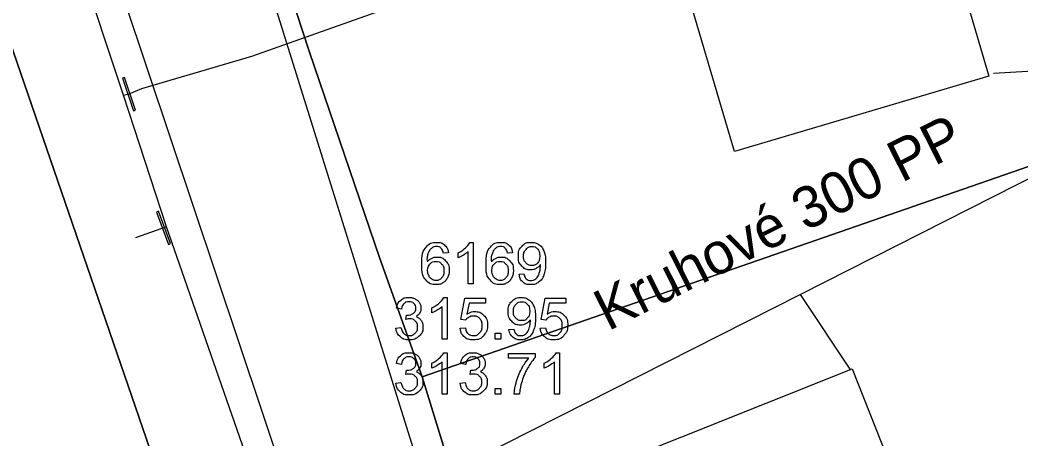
# Model space of a CAD drawing. Extents: x -562248 to -562040, y -1079385 to -1079027.
# Drawn here: x -562123.63 to -562087.3, y -1079164.97 to -1079149.79 of the extents above; entities that cross this region are included whole.
import ezdxf

# ---------------------------------------------------------------- set-up
doc = ezdxf.new("R2010")
doc.units = 0
for name, color, linetype in [('Armatura vodovodní', 7, 'Continuous'), ('Kanalizační přípojka', 7, 'Continuous'), ('Kanalizační stoka', 7, 'Continuous'), ('Parcela-polygon', 7, 'Continuous'), ('Popis kmenové stoky', 7, 'Continuous'), ('Popis šachty', 7, 'Continuous'), ('Vodovodní přípojka', 7, 'Continuous'), ('Vodovodní řad', 7, 'Continuous')]:
    doc.layers.add(name, color=color, linetype=linetype)

msp = doc.modelspace()

# ---------------------------------------------------------------- linework, layer by layer
at = {"layer": 'Armatura vodovodní'}
for points in [[(-562119.512, -1079153.079), (-562119.438, -1079153.054), (-562119.841, -1079151.871), (-562119.915, -1079151.896)], [(-562118.243, -1079157.919), (-562118.17, -1079157.891), (-562118.608, -1079156.721), (-562118.681, -1079156.748)]]:
    msp.add_lwpolyline(points, close=True, dxfattribs=at)
at = {"layer": 'Kanalizační přípojka'}
for points in [[(-562088.3, -1079151.71), (-562084.597, -1079151.5)], [(-562093.48, -1079162.48), (-562095.299, -1079159.731)]]:
    msp.add_lwpolyline(points, dxfattribs=at)
at = {"layer": 'Kanalizační stoka'}
for points in [[(-562118.27, -1079136.83), (-562108.95, -1079166.63)], [(-562098.95, -1079211.35), (-562123.19, -1079139.07)], [(-562083.94, -1079153.99), (-562095.303, -1079159.733), (-562108.95, -1079166.63)]]:
    msp.add_lwpolyline(points, dxfattribs=at)
at = {"layer": 'Parcela-polygon'}
for points in [[(-562074.7, -1079253.09), (-562081.96, -1079237.32), (-562088.81, -1079221.44), (-562094.66, -1079207.06), (-562098.96, -1079196.12), (-562103.67, -1079183.92), (-562101.64, -1079183.14), (-562108.26, -1079165.24), (-562109.03, -1079162.72), (-562110.57, -1079158.43), (-562113.13, -1079150.92), (-562115.47, -1079143.79), (-562118.94, -1079132.53), (-562120.22, -1079128.2), (-562121.94, -1079119.29), (-562122.55, -1079115.89), (-562122.79, -1079112.89), (-562122.92, -1079108.96), (-562122.69, -1079105.05), (-562122.05, -1079101.16)], [(-562097.98, -1079104.526), (-562122.92, -1079108.96), (-562122.79, -1079112.89), (-562122.55, -1079115.89), (-562121.94, -1079119.29), (-562120.22, -1079128.2), (-562118.94, -1079132.53), (-562115.47, -1079143.79), (-562113.13, -1079150.92), (-562110.57, -1079158.43), (-562109.03, -1079162.72), (-562081.378, -1079153.144)], [(-562101.27, -1079108.39), (-562097, -1079122.85), (-562092.73, -1079137.34), (-562088.46, -1079151.82), (-562097.7, -1079154.55), (-562101.98, -1079140.06), (-562106.25, -1079125.58), (-562110.52, -1079111.1), (-562101.27, -1079108.39)], [(-562130.204, -1079213.482), (-562129.52, -1079213.24), (-562126.56, -1079212.06), (-562110.18, -1079204.89), (-562109.412, -1079204.67), (-562108.694, -1079204.319), (-562108.049, -1079203.848), (-562107.496, -1079203.271), (-562107.054, -1079202.606), (-562106.734, -1079201.874), (-562106.547, -1079201.097), (-562106.5, -1079200.3), (-562107.01, -1079197.84), (-562112.9, -1079182.58), (-562117.83, -1079168.5), (-562124.14, -1079150.14), (-562125.7, -1079148.16), (-562127.71, -1079147.6), (-562130.14, -1079147.9), (-562151.942, -1079151.733)], [(-562151.942, -1079151.733), (-562130.14, -1079147.9), (-562127.71, -1079147.6), (-562125.7, -1079148.16), (-562124.14, -1079150.14), (-562117.83, -1079168.5), (-562112.9, -1079182.58), (-562107.01, -1079197.84), (-562106.5, -1079200.3), (-562100.28, -1079214.7), (-562095.19, -1079227.16), (-562092.25, -1079234.14), (-562087.93, -1079243.96)], [(-562081.378, -1079153.144), (-562109.03, -1079162.72), (-562108.26, -1079165.24), (-562101.64, -1079183.14), (-562103.67, -1079183.92), (-562098.96, -1079196.12), (-562094.66, -1079207.06), (-562088.81, -1079221.44), (-562081.96, -1079237.32), (-562074.7, -1079253.09), (-562050.734, -1079242.89)], [(-562096.6, -1079181.53), (-562102.73, -1079166.14), (-562093.43, -1079162.43), (-562091.11, -1079168.27), (-562089.23, -1079167.52), (-562087.59, -1079171.57), (-562089.45, -1079172.36), (-562087.31, -1079177.84), (-562084.66, -1079184.52)]]:
    msp.add_lwpolyline(points, dxfattribs=at)
for points in [[(-562092.73, -1079137.34), (-562088.46, -1079151.82), (-562097.7, -1079154.55), (-562101.98, -1079140.06)], [(-562091.11, -1079168.27), (-562089.23, -1079167.52), (-562087.59, -1079171.57), (-562089.45, -1079172.36), (-562087.31, -1079177.84), (-562096.6, -1079181.53), (-562102.73, -1079166.14), (-562093.43, -1079162.43)]]:
    msp.add_lwpolyline(points, close=True, dxfattribs=at)
at = {"layer": 'Popis šachty'}
for points in [[(-562107.298, -1079157.846), (-562107.18, -1079157.846), (-562107.18, -1079159.352)], [(-562108.081, -1079158.22), (-562108.264, -1079158.235)], [(-562107.732, -1079158.401), (-562107.732, -1079158.223)], [(-562107.18, -1079159.352), (-562107.364, -1079159.352), (-562107.364, -1079158.179)], [(-562105.751, -1079158.22), (-562105.933, -1079158.235)], [(-562105.515, -1079159.004), (-562105.338, -1079158.988)], [(-562108.248, -1079159.846), (-562108.129, -1079159.846), (-562108.129, -1079161.352)], [(-562107.451, -1079160.665), (-562107.624, -1079160.642), (-562107.479, -1079159.871), (-562106.733, -1079159.871), (-562106.733, -1079160.047), (-562107.331, -1079160.047), (-562107.412, -1079160.45)], [(-562104.539, -1079160.665), (-562104.712, -1079160.642), (-562104.567, -1079159.871), (-562103.821, -1079159.871), (-562103.821, -1079160.047), (-562104.419, -1079160.047), (-562104.5, -1079160.45)], [(-562109.783, -1079160.268), (-562109.968, -1079160.235)], [(-562108.681, -1079160.401), (-562108.681, -1079160.223)], [(-562108.129, -1079161.352), (-562108.313, -1079161.352), (-562108.313, -1079160.179)], [(-562109.623, -1079160.641), (-562109.602, -1079160.48)], [(-562109.986, -1079160.954), (-562109.802, -1079160.93)], [(-562107.657, -1079160.959), (-562107.464, -1079160.943)], [(-562104.745, -1079160.959), (-562104.552, -1079160.943)], [(-562106.389, -1079161.352), (-562106.389, -1079161.143), (-562106.18, -1079161.143), (-562106.18, -1079161.352), (-562106.389, -1079161.352)], [(-562105.883, -1079161.004), (-562105.705, -1079160.988)], [(-562108.248, -1079161.846), (-562108.129, -1079161.846), (-562108.129, -1079163.352)], [(-562105.897, -1079162.049), (-562105.897, -1079161.871), (-562104.927, -1079161.871), (-562104.927, -1079162.015)], [(-562105.163, -1079162.049), (-562105.897, -1079162.049)], [(-562104.171, -1079161.846), (-562104.052, -1079161.846), (-562104.052, -1079163.352)], [(-562109.783, -1079162.268), (-562109.968, -1079162.235)], [(-562108.681, -1079162.401), (-562108.681, -1079162.223)], [(-562108.129, -1079163.352), (-562108.313, -1079163.352), (-562108.313, -1079162.179)], [(-562107.453, -1079162.268), (-562107.637, -1079162.235)], [(-562104.604, -1079162.401), (-562104.604, -1079162.223)], [(-562104.052, -1079163.352), (-562104.236, -1079163.352), (-562104.236, -1079162.179)], [(-562109.623, -1079162.641), (-562109.602, -1079162.48)], [(-562107.293, -1079162.641), (-562107.272, -1079162.48)], [(-562109.986, -1079162.954), (-562109.802, -1079162.93)], [(-562107.656, -1079162.954), (-562107.472, -1079162.93)], [(-562106.389, -1079163.352), (-562106.389, -1079163.143), (-562106.18, -1079163.143), (-562106.18, -1079163.352), (-562106.389, -1079163.352)], [(-562105.498, -1079163.352), (-562105.688, -1079163.352)]]:
    msp.add_lwpolyline(points, dxfattribs=at)
for points in [[(-562108.264, -1079158.235), (-562108.288, -1079158.126), (-562108.333, -1079158.076), (-562108.408, -1079157.997), (-562108.518, -1079157.997), (-562108.606, -1079157.997), (-562108.673, -1079158.046), (-562108.76, -1079158.11), (-562108.81, -1079158.232), (-562108.861, -1079158.353), (-562108.863, -1079158.578), (-562108.796, -1079158.477), (-562108.7, -1079158.428), (-562108.603, -1079158.379), (-562108.498, -1079158.379), (-562108.313, -1079158.379), (-562108.184, -1079158.514), (-562108.054, -1079158.65), (-562108.054, -1079158.865), (-562108.054, -1079159.006), (-562108.115, -1079159.127), (-562108.176, -1079159.248), (-562108.283, -1079159.313), (-562108.389, -1079159.377), (-562108.524, -1079159.377), (-562108.755, -1079159.377), (-562108.9, -1079159.208), (-562109.046, -1079159.039), (-562109.046, -1079158.65), (-562109.046, -1079158.215), (-562108.885, -1079158.018), (-562108.744, -1079157.846), (-562108.507, -1079157.846), (-562108.33, -1079157.846), (-562108.216, -1079157.946), (-562108.103, -1079158.045), (-562108.081, -1079158.22)], [(-562107.732, -1079158.223), (-562107.577, -1079158.15), (-562107.462, -1079158.047), (-562107.346, -1079157.943), (-562107.298, -1079157.846)], [(-562105.933, -1079158.235), (-562105.958, -1079158.126), (-562106.003, -1079158.076), (-562106.078, -1079157.997), (-562106.188, -1079157.997), (-562106.276, -1079157.997), (-562106.343, -1079158.046), (-562106.43, -1079158.11), (-562106.48, -1079158.232), (-562106.531, -1079158.353), (-562106.533, -1079158.578), (-562106.466, -1079158.477), (-562106.37, -1079158.428), (-562106.273, -1079158.379), (-562106.168, -1079158.379), (-562105.983, -1079158.379), (-562105.854, -1079158.514), (-562105.724, -1079158.65), (-562105.724, -1079158.865), (-562105.724, -1079159.006), (-562105.785, -1079159.127), (-562105.846, -1079159.248), (-562105.953, -1079159.313), (-562106.059, -1079159.377), (-562106.194, -1079159.377), (-562106.425, -1079159.377), (-562106.57, -1079159.208), (-562106.715, -1079159.039), (-562106.715, -1079158.65), (-562106.715, -1079158.215), (-562106.555, -1079158.018), (-562106.414, -1079157.846), (-562106.177, -1079157.846), (-562105.999, -1079157.846), (-562105.886, -1079157.946), (-562105.773, -1079158.045), (-562105.751, -1079158.22)], [(-562105.338, -1079158.988), (-562105.315, -1079159.113), (-562105.252, -1079159.17), (-562105.189, -1079159.226), (-562105.09, -1079159.226), (-562105.005, -1079159.226), (-562104.941, -1079159.187), (-562104.876, -1079159.148), (-562104.836, -1079159.083), (-562104.795, -1079159.018), (-562104.768, -1079158.908), (-562104.74, -1079158.797), (-562104.74, -1079158.682), (-562104.74, -1079158.67), (-562104.741, -1079158.646), (-562104.796, -1079158.734), (-562104.892, -1079158.788), (-562104.987, -1079158.843), (-562105.099, -1079158.843), (-562105.285, -1079158.843), (-562105.414, -1079158.708), (-562105.542, -1079158.573), (-562105.542, -1079158.352), (-562105.542, -1079158.124), (-562105.408, -1079157.985), (-562105.274, -1079157.846), (-562105.071, -1079157.846), (-562104.925, -1079157.846), (-562104.804, -1079157.925), (-562104.683, -1079158.004), (-562104.62, -1079158.149), (-562104.557, -1079158.295), (-562104.557, -1079158.571), (-562104.557, -1079158.859), (-562104.619, -1079159.029), (-562104.682, -1079159.199), (-562104.805, -1079159.288), (-562104.928, -1079159.377), (-562105.094, -1079159.377), (-562105.27, -1079159.377), (-562105.381, -1079159.279), (-562105.493, -1079159.181), (-562105.515, -1079159.004)], [(-562104.762, -1079158.343), (-562104.762, -1079158.184), (-562104.846, -1079158.091), (-562104.929, -1079157.998), (-562105.048, -1079157.998), (-562105.172, -1079157.998), (-562105.262, -1079158.099), (-562105.353, -1079158.199), (-562105.353, -1079158.358), (-562105.353, -1079158.502), (-562105.267, -1079158.591), (-562105.181, -1079158.681), (-562105.054, -1079158.681), (-562104.926, -1079158.681), (-562104.844, -1079158.591), (-562104.762, -1079158.502), (-562104.762, -1079158.343)], [(-562107.364, -1079158.179), (-562107.43, -1079158.242), (-562107.538, -1079158.305), (-562107.646, -1079158.369), (-562107.732, -1079158.401)], [(-562108.834, -1079158.866), (-562108.834, -1079158.961), (-562108.794, -1079159.048), (-562108.753, -1079159.135), (-562108.681, -1079159.181), (-562108.609, -1079159.226), (-562108.528, -1079159.226), (-562108.411, -1079159.226), (-562108.328, -1079159.132), (-562108.244, -1079159.038), (-562108.244, -1079158.876), (-562108.244, -1079158.72), (-562108.327, -1079158.631), (-562108.409, -1079158.541), (-562108.535, -1079158.541), (-562108.66, -1079158.541), (-562108.747, -1079158.631), (-562108.834, -1079158.72), (-562108.834, -1079158.866)], [(-562106.504, -1079158.866), (-562106.504, -1079158.961), (-562106.464, -1079159.048), (-562106.423, -1079159.135), (-562106.351, -1079159.181), (-562106.279, -1079159.226), (-562106.198, -1079159.226), (-562106.081, -1079159.226), (-562105.998, -1079159.132), (-562105.914, -1079159.038), (-562105.914, -1079158.876), (-562105.914, -1079158.72), (-562105.997, -1079158.631), (-562106.079, -1079158.541), (-562106.205, -1079158.541), (-562106.33, -1079158.541), (-562106.417, -1079158.631), (-562106.504, -1079158.72), (-562106.504, -1079158.866)], [(-562109.968, -1079160.235), (-562109.934, -1079160.05), (-562109.814, -1079159.948), (-562109.694, -1079159.846), (-562109.516, -1079159.846), (-562109.393, -1079159.846), (-562109.29, -1079159.899), (-562109.186, -1079159.951), (-562109.132, -1079160.042), (-562109.077, -1079160.133), (-562109.077, -1079160.235), (-562109.077, -1079160.332), (-562109.129, -1079160.412), (-562109.181, -1079160.492), (-562109.284, -1079160.539), (-562109.151, -1079160.569), (-562109.077, -1079160.666), (-562109.004, -1079160.763), (-562109.004, -1079160.908), (-562109.004, -1079161.104), (-562109.147, -1079161.241), (-562109.29, -1079161.377), (-562109.509, -1079161.377), (-562109.707, -1079161.377), (-562109.837, -1079161.259), (-562109.967, -1079161.141), (-562109.986, -1079160.954)], [(-562108.681, -1079160.223), (-562108.527, -1079160.15), (-562108.411, -1079160.047), (-562108.296, -1079159.943), (-562108.248, -1079159.846)], [(-562105.705, -1079160.988), (-562105.683, -1079161.113), (-562105.619, -1079161.17), (-562105.556, -1079161.226), (-562105.457, -1079161.226), (-562105.372, -1079161.226), (-562105.308, -1079161.187), (-562105.244, -1079161.148), (-562105.203, -1079161.083), (-562105.163, -1079161.018), (-562105.135, -1079160.908), (-562105.107, -1079160.797), (-562105.107, -1079160.682), (-562105.107, -1079160.67), (-562105.109, -1079160.646), (-562105.164, -1079160.734), (-562105.259, -1079160.788), (-562105.355, -1079160.843), (-562105.466, -1079160.843), (-562105.652, -1079160.843), (-562105.781, -1079160.708), (-562105.91, -1079160.573), (-562105.91, -1079160.352), (-562105.91, -1079160.124), (-562105.776, -1079159.985), (-562105.641, -1079159.846), (-562105.439, -1079159.846), (-562105.292, -1079159.846), (-562105.171, -1079159.925), (-562105.05, -1079160.004), (-562104.987, -1079160.149), (-562104.924, -1079160.295), (-562104.924, -1079160.571), (-562104.924, -1079160.859), (-562104.987, -1079161.029), (-562105.049, -1079161.199), (-562105.172, -1079161.288), (-562105.296, -1079161.377), (-562105.461, -1079161.377), (-562105.637, -1079161.377), (-562105.749, -1079161.279), (-562105.86, -1079161.181), (-562105.883, -1079161.004)], [(-562109.602, -1079160.48), (-562109.584, -1079160.482), (-562109.573, -1079160.482), (-562109.455, -1079160.482), (-562109.361, -1079160.42), (-562109.267, -1079160.359), (-562109.267, -1079160.231), (-562109.267, -1079160.13), (-562109.335, -1079160.064), (-562109.404, -1079159.997), (-562109.512, -1079159.997), (-562109.62, -1079159.997), (-562109.691, -1079160.065), (-562109.763, -1079160.133), (-562109.783, -1079160.268)], [(-562108.313, -1079160.179), (-562108.38, -1079160.242), (-562108.488, -1079160.305), (-562108.595, -1079160.369), (-562108.681, -1079160.401)], [(-562105.129, -1079160.343), (-562105.129, -1079160.184), (-562105.213, -1079160.091), (-562105.297, -1079159.998), (-562105.416, -1079159.998), (-562105.539, -1079159.998), (-562105.63, -1079160.099), (-562105.72, -1079160.199), (-562105.72, -1079160.358), (-562105.72, -1079160.502), (-562105.634, -1079160.591), (-562105.548, -1079160.681), (-562105.421, -1079160.681), (-562105.293, -1079160.681), (-562105.211, -1079160.591), (-562105.129, -1079160.502), (-562105.129, -1079160.343)], [(-562107.412, -1079160.45), (-562107.277, -1079160.356), (-562107.129, -1079160.356), (-562106.932, -1079160.356), (-562106.797, -1079160.492), (-562106.662, -1079160.628), (-562106.662, -1079160.843), (-562106.662, -1079161.046), (-562106.781, -1079161.195), (-562106.925, -1079161.377), (-562107.175, -1079161.377), (-562107.38, -1079161.377), (-562107.509, -1079161.262), (-562107.638, -1079161.148), (-562107.657, -1079160.959)], [(-562107.464, -1079160.943), (-562107.442, -1079161.084), (-562107.364, -1079161.155), (-562107.286, -1079161.226), (-562107.175, -1079161.226), (-562107.041, -1079161.226), (-562106.949, -1079161.126), (-562106.858, -1079161.025), (-562106.858, -1079160.859), (-562106.858, -1079160.701), (-562106.946, -1079160.61), (-562107.034, -1079160.518), (-562107.178, -1079160.518), (-562107.268, -1079160.518), (-562107.339, -1079160.559), (-562107.41, -1079160.6), (-562107.451, -1079160.665)], [(-562104.5, -1079160.45), (-562104.365, -1079160.356), (-562104.217, -1079160.356), (-562104.02, -1079160.356), (-562103.885, -1079160.492), (-562103.75, -1079160.628), (-562103.75, -1079160.843), (-562103.75, -1079161.046), (-562103.869, -1079161.195), (-562104.013, -1079161.377), (-562104.263, -1079161.377), (-562104.468, -1079161.377), (-562104.597, -1079161.262), (-562104.727, -1079161.148), (-562104.745, -1079160.959)], [(-562104.552, -1079160.943), (-562104.53, -1079161.084), (-562104.452, -1079161.155), (-562104.374, -1079161.226), (-562104.263, -1079161.226), (-562104.129, -1079161.226), (-562104.037, -1079161.126), (-562103.946, -1079161.025), (-562103.946, -1079160.859), (-562103.946, -1079160.701), (-562104.034, -1079160.61), (-562104.122, -1079160.518), (-562104.266, -1079160.518), (-562104.356, -1079160.518), (-562104.427, -1079160.559), (-562104.498, -1079160.6), (-562104.539, -1079160.665)], [(-562109.802, -1079160.93), (-562109.77, -1079161.087), (-562109.694, -1079161.156), (-562109.618, -1079161.225), (-562109.508, -1079161.225), (-562109.378, -1079161.225), (-562109.288, -1079161.135), (-562109.199, -1079161.045), (-562109.199, -1079160.912), (-562109.199, -1079160.785), (-562109.282, -1079160.703), (-562109.365, -1079160.62), (-562109.493, -1079160.62), (-562109.545, -1079160.62), (-562109.623, -1079160.641)], [(-562109.968, -1079162.235), (-562109.934, -1079162.05), (-562109.814, -1079161.948), (-562109.694, -1079161.846), (-562109.516, -1079161.846), (-562109.393, -1079161.846), (-562109.29, -1079161.899), (-562109.186, -1079161.951), (-562109.132, -1079162.042), (-562109.077, -1079162.133), (-562109.077, -1079162.235), (-562109.077, -1079162.332), (-562109.129, -1079162.412), (-562109.181, -1079162.492), (-562109.284, -1079162.539), (-562109.151, -1079162.569), (-562109.077, -1079162.666), (-562109.004, -1079162.763), (-562109.004, -1079162.908), (-562109.004, -1079163.104), (-562109.147, -1079163.241), (-562109.29, -1079163.377), (-562109.509, -1079163.377), (-562109.707, -1079163.377), (-562109.837, -1079163.259), (-562109.967, -1079163.141), (-562109.986, -1079162.954)], [(-562109.602, -1079162.48), (-562109.584, -1079162.482), (-562109.573, -1079162.482), (-562109.455, -1079162.482), (-562109.361, -1079162.42), (-562109.267, -1079162.359), (-562109.267, -1079162.231), (-562109.267, -1079162.13), (-562109.335, -1079162.064), (-562109.404, -1079161.997), (-562109.512, -1079161.997), (-562109.62, -1079161.997), (-562109.691, -1079162.065), (-562109.763, -1079162.133), (-562109.783, -1079162.268)], [(-562108.681, -1079162.223), (-562108.527, -1079162.15), (-562108.411, -1079162.047), (-562108.296, -1079161.943), (-562108.248, -1079161.846)], [(-562107.637, -1079162.235), (-562107.604, -1079162.05), (-562107.484, -1079161.948), (-562107.364, -1079161.846), (-562107.186, -1079161.846), (-562107.063, -1079161.846), (-562106.96, -1079161.899), (-562106.856, -1079161.951), (-562106.802, -1079162.042), (-562106.747, -1079162.133), (-562106.747, -1079162.235), (-562106.747, -1079162.332), (-562106.799, -1079162.412), (-562106.851, -1079162.492), (-562106.954, -1079162.539), (-562106.821, -1079162.569), (-562106.747, -1079162.666), (-562106.674, -1079162.763), (-562106.674, -1079162.908), (-562106.674, -1079163.104), (-562106.817, -1079163.241), (-562106.96, -1079163.377), (-562107.179, -1079163.377), (-562107.376, -1079163.377), (-562107.507, -1079163.259), (-562107.637, -1079163.141), (-562107.656, -1079162.954)], [(-562107.272, -1079162.48), (-562107.254, -1079162.482), (-562107.243, -1079162.482), (-562107.125, -1079162.482), (-562107.031, -1079162.42), (-562106.937, -1079162.359), (-562106.937, -1079162.231), (-562106.937, -1079162.13), (-562107.005, -1079162.064), (-562107.074, -1079161.997), (-562107.182, -1079161.997), (-562107.29, -1079161.997), (-562107.361, -1079162.065), (-562107.433, -1079162.133), (-562107.453, -1079162.268)], [(-562105.688, -1079163.352), (-562105.685, -1079163.175), (-562105.619, -1079162.924), (-562105.552, -1079162.674), (-562105.428, -1079162.441), (-562105.304, -1079162.208), (-562105.163, -1079162.049)], [(-562104.927, -1079162.015), (-562105.07, -1079162.167), (-562105.211, -1079162.42), (-562105.351, -1079162.673), (-562105.428, -1079162.94), (-562105.483, -1079163.128), (-562105.498, -1079163.352)], [(-562104.604, -1079162.223), (-562104.45, -1079162.15), (-562104.334, -1079162.047), (-562104.219, -1079161.943), (-562104.171, -1079161.846)], [(-562108.313, -1079162.179), (-562108.38, -1079162.242), (-562108.488, -1079162.305), (-562108.595, -1079162.369), (-562108.681, -1079162.401)], [(-562104.236, -1079162.179), (-562104.303, -1079162.242), (-562104.411, -1079162.305), (-562104.518, -1079162.369), (-562104.604, -1079162.401)], [(-562109.802, -1079162.93), (-562109.77, -1079163.087), (-562109.694, -1079163.156), (-562109.618, -1079163.225), (-562109.508, -1079163.225), (-562109.378, -1079163.225), (-562109.288, -1079163.135), (-562109.199, -1079163.045), (-562109.199, -1079162.912), (-562109.199, -1079162.785), (-562109.282, -1079162.703), (-562109.365, -1079162.62), (-562109.493, -1079162.62), (-562109.545, -1079162.62), (-562109.623, -1079162.641)], [(-562107.472, -1079162.93), (-562107.44, -1079163.087), (-562107.364, -1079163.156), (-562107.288, -1079163.225), (-562107.178, -1079163.225), (-562107.048, -1079163.225), (-562106.958, -1079163.135), (-562106.869, -1079163.045), (-562106.869, -1079162.912), (-562106.869, -1079162.785), (-562106.952, -1079162.703), (-562107.035, -1079162.62), (-562107.163, -1079162.62), (-562107.215, -1079162.62), (-562107.293, -1079162.641)]]:
    msp.add_open_spline(points, degree=3, dxfattribs=at)
at = {"layer": 'Vodovodní přípojka'}
for points in [[(-562119.874, -1079152.505), (-562119.666, -1079152.467), (-562119.205, -1079152.27), (-562115.221, -1079151.096), (-562100.139, -1079145.758)], [(-562118.308, -1079157.281), (-562119.433, -1079157.679)]]:
    msp.add_lwpolyline(points, dxfattribs=at)
at = {"layer": 'Vodovodní řad'}
msp.add_lwpolyline([(-562104.508, -1079195.68), (-562105.675, -1079193.599), (-562106.045, -1079192.495), (-562108.292, -1079185.845), (-562110.54, -1079179.194), (-562111.609, -1079176.901), (-562113.474, -1079171.283), (-562115.559, -1079165.192), (-562118.308, -1079157.281), (-562119.874, -1079152.505), (-562123.128, -1079142.718), (-562124.818, -1079137.317), (-562126.048, -1079133.176), (-562126.972, -1079129.683), (-562127.886, -1079125.317), (-562128.484, -1079121.808), (-562129.183, -1079117.074), (-562129.389, -1079112.24), (-562129.474, -1079106.997), (-562129.319, -1079103.524), (-562128.819, -1079100.288), (-562128.175, -1079096.35), (-562128.115, -1079096.032)], dxfattribs=at)

# ---------------------------------------------------------------- texts
at = {"layer": 'Popis kmenové stoky'}
msp.add_text('Kruhové 300 PP', height=1.5, rotation=26.8126, dxfattribs=at).set_placement((-562102.286, -1079161.079))

doc.saveas('drawing.dxf')
